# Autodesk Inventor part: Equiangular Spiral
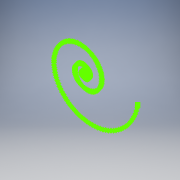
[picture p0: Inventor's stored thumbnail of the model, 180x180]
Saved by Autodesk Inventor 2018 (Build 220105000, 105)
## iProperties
Created: 2008-02
Part Number: Equiangular Spiral
Document SubType Name: Modeling
Designer: Autodesk, Inc.
Density: 1 g/cm^3
Material: Generic
Appearance: Default
Author: Autodesk, Inc.
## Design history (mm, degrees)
sketch "Sketch1"
  geometry: 301 further points
  constraints: 301 other
